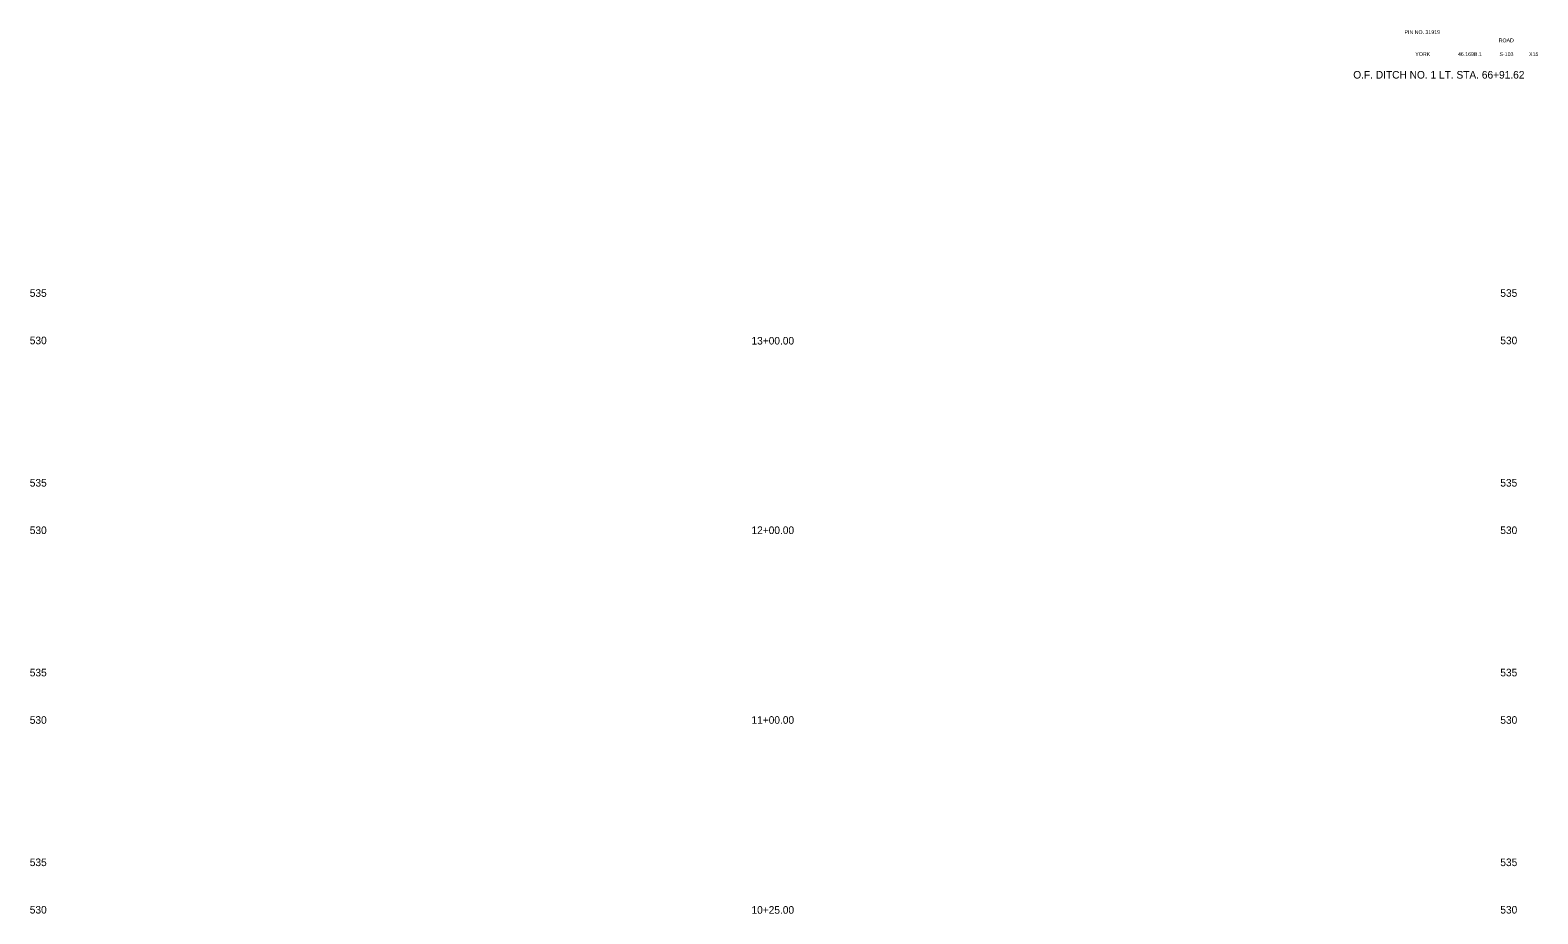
# Model space of a CAD drawing. Extents: x 1002 to 1161, y 1010 to 1103.
import ezdxf

# ---------------------------------------------------------------- set-up
doc = ezdxf.new("R2010")
doc.units = 0
for name, color, linetype in [('Level 25', 7, 'Continuous'), ('Level 41', 7, 'Continuous'), ('Level 56', 7, 'Continuous')]:
    doc.layers.add(name, color=color, linetype=linetype)

msp = doc.modelspace()

# ---------------------------------------------------------------- texts
at = {"layer": 'Level 25'}
for s, p in [('13+00.00', (1077.7, 1070.07)), ('12+00.00', (1077.7, 1050.1)), ('11+00.00', (1077.7, 1030.1)), ('10+25.00', (1077.7, 1010.08))]:
    msp.add_text(s, height=0.8, dxfattribs=at).set_placement(p)
at = {"layer": 'Level 41'}
for s, height, p in [('PIN NO. 31919', 0.4, (1146.53, 1102.8)), ('ROAD', 0.4, (1156.46, 1101.93)), ('YORK', 0.4, (1147.67, 1100.48)), ('46.169B.1', 0.4, (1152.16, 1100.48)), ('S-103', 0.4, (1156.54, 1100.48)), ('X15', 0.4, (1159.66, 1100.48)), ('O.F. DITCH NO. 1 LT. STA. 66+91.62', 0.8, (1141.13, 1098.1))]:
    msp.add_text(s, height=height, dxfattribs=at).set_placement(p)
at = {"layer": 'Level 56'}
for s, p in [('535', (1001.63, 1075.1)), ('535', (1156.63, 1075.1)), ('530', (1001.63, 1070.1)), ('530', (1156.63, 1070.1)), ('535', (1001.63, 1055.1)), ('535', (1156.63, 1055.1)), ('530', (1001.63, 1050.1)), ('530', (1156.63, 1050.1)), ('535', (1001.63, 1035.1)), ('535', (1156.63, 1035.1)), ('530', (1001.63, 1030.1)), ('530', (1156.63, 1030.1)), ('535', (1001.63, 1015.1)), ('535', (1156.63, 1015.1)), ('530', (1001.63, 1010.1)), ('530', (1156.63, 1010.1))]:
    msp.add_text(s, height=0.8, dxfattribs=at).set_placement(p)

doc.saveas('drawing.dxf')
